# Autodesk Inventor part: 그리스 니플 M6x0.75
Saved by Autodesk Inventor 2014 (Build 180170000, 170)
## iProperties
Created: 2026-03
Part Number: 그리스 니플 M6x0.75
Material: 일반
Document SubType Name: Modeling
Designer: dg
Density: 1 g/cm^3
Appearance: 기본값
Author: dg
Author: jhkim
Description: 윤활 니플, 원추 유형 A
Creation Date: 2025-06-27
Sending System: Autodesk Inventor 2026
Preprocessor: ST-DEVELOPER v20.1
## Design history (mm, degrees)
node "그리스 니플 M6x0.751"
body "Solid1"
node "기준1"
